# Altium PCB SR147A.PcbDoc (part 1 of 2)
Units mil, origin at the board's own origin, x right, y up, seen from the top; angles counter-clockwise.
Board outline 3000 x 3006 mil, 4 copper layers (Top Layer, Signal Layer 1, Signal Layer 2, Bottom Layer), stack 60.434 mil thick; 65 components, 14 nets, 93 pads, 851 vias.
Unrouted connection lines stored in the file: 2.
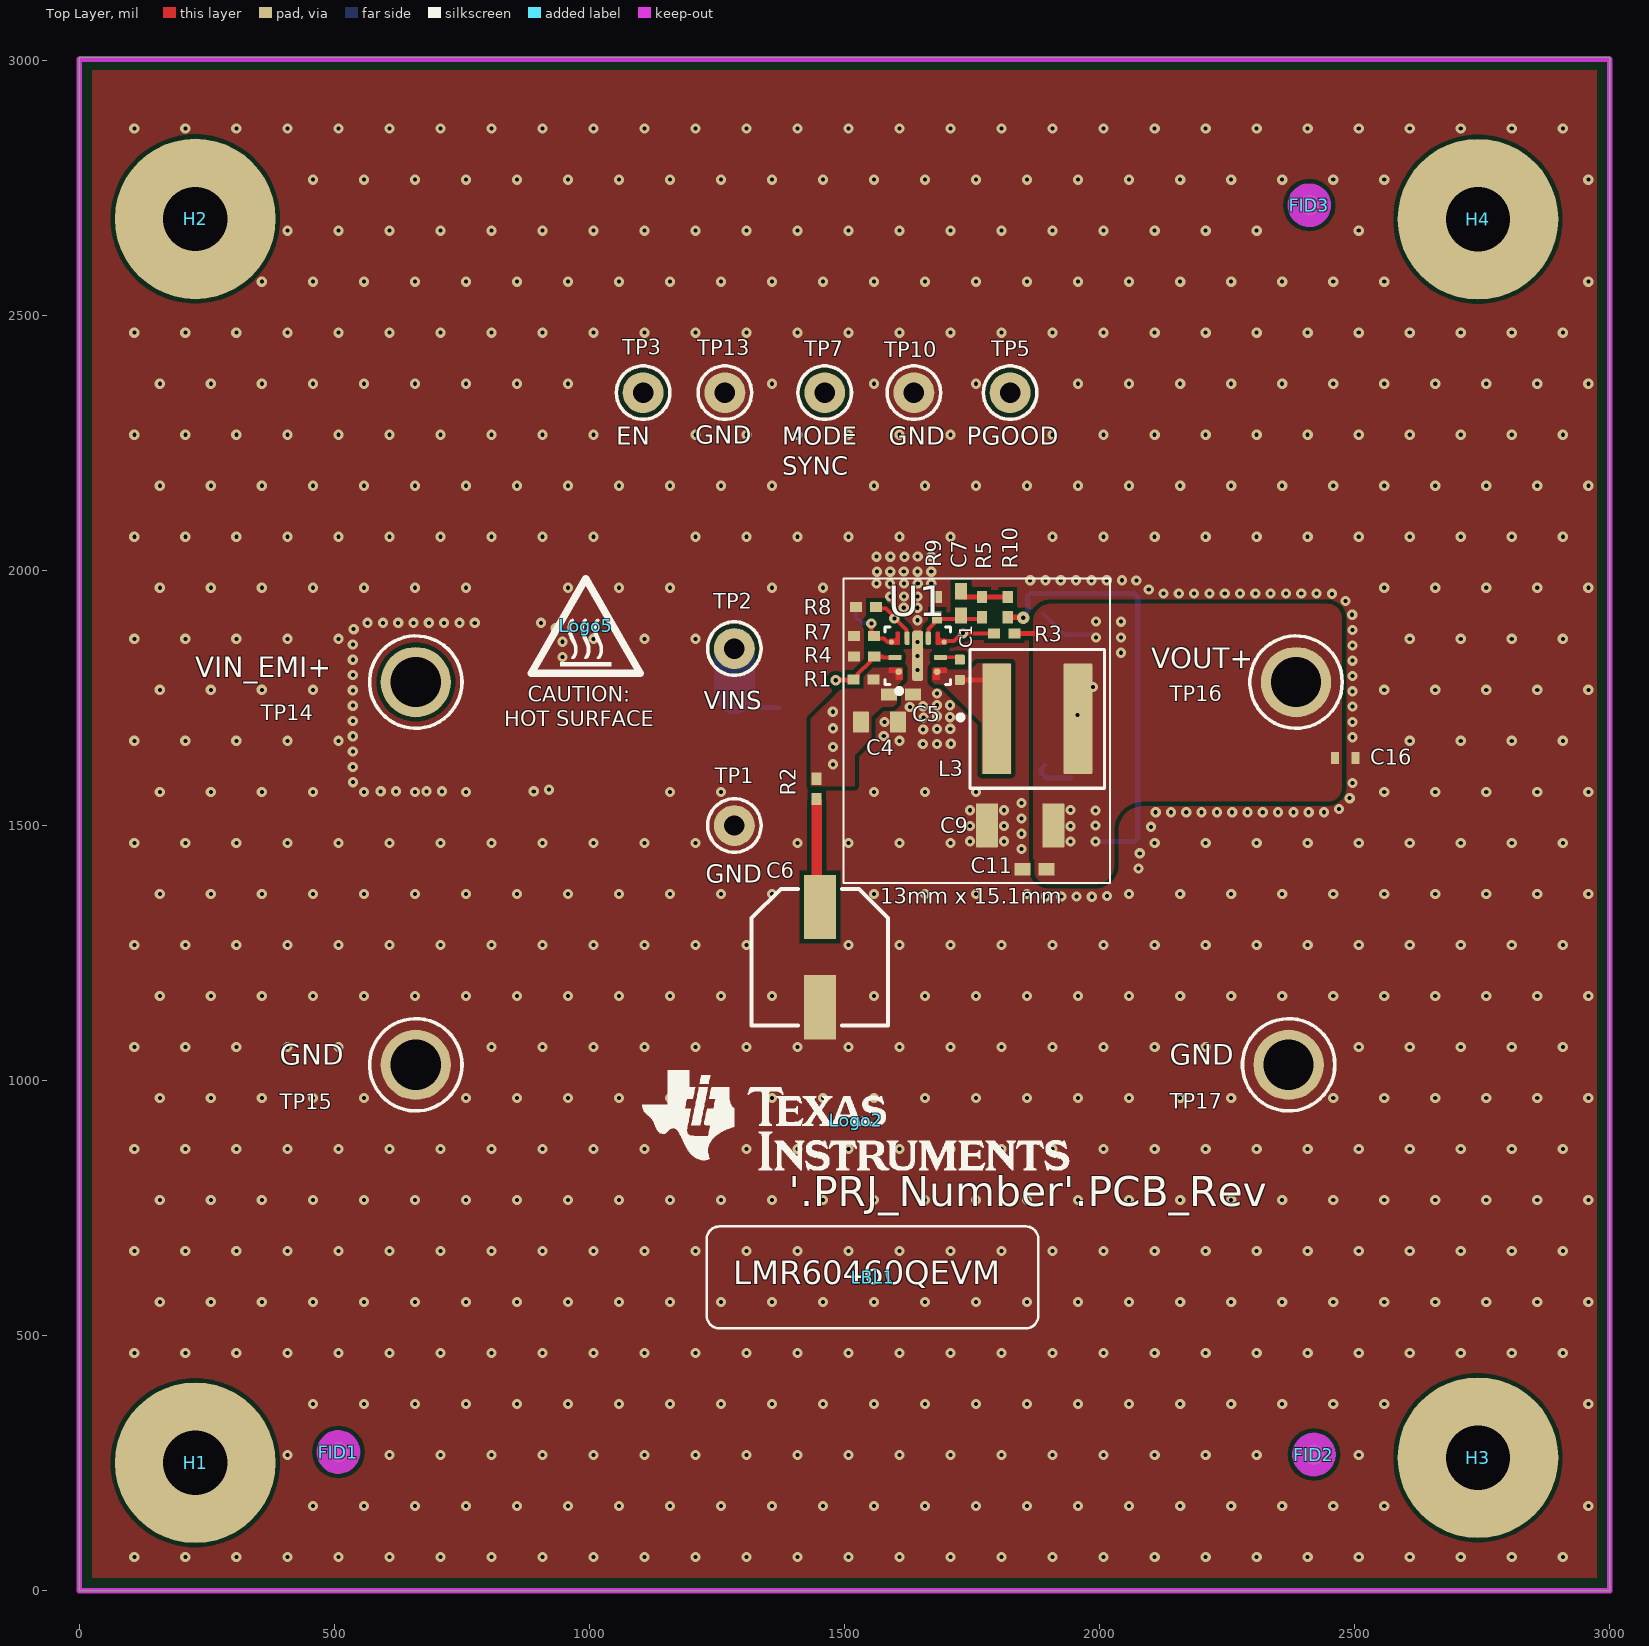
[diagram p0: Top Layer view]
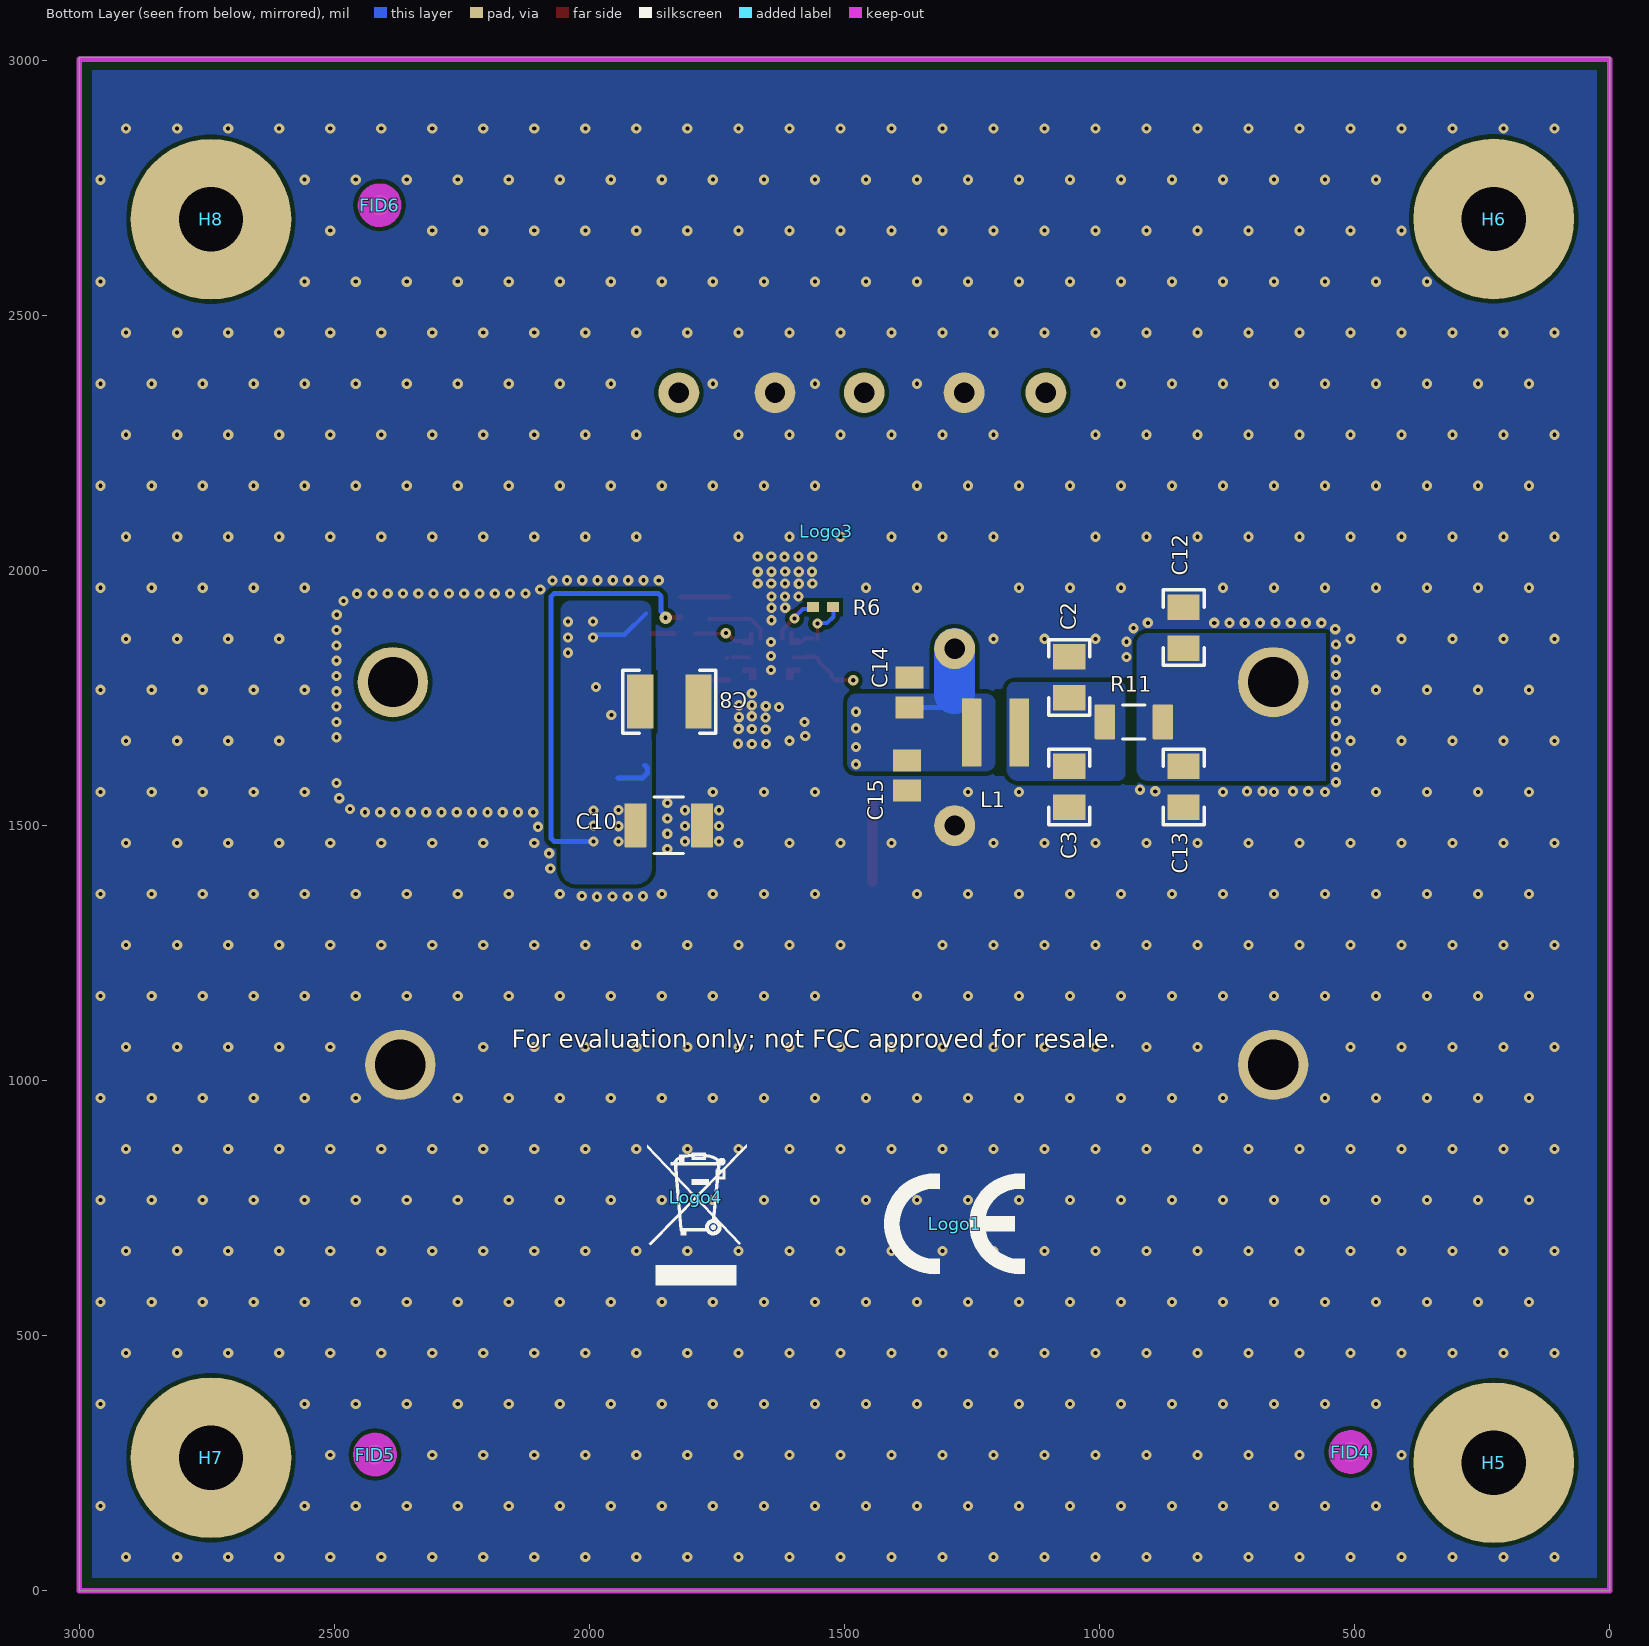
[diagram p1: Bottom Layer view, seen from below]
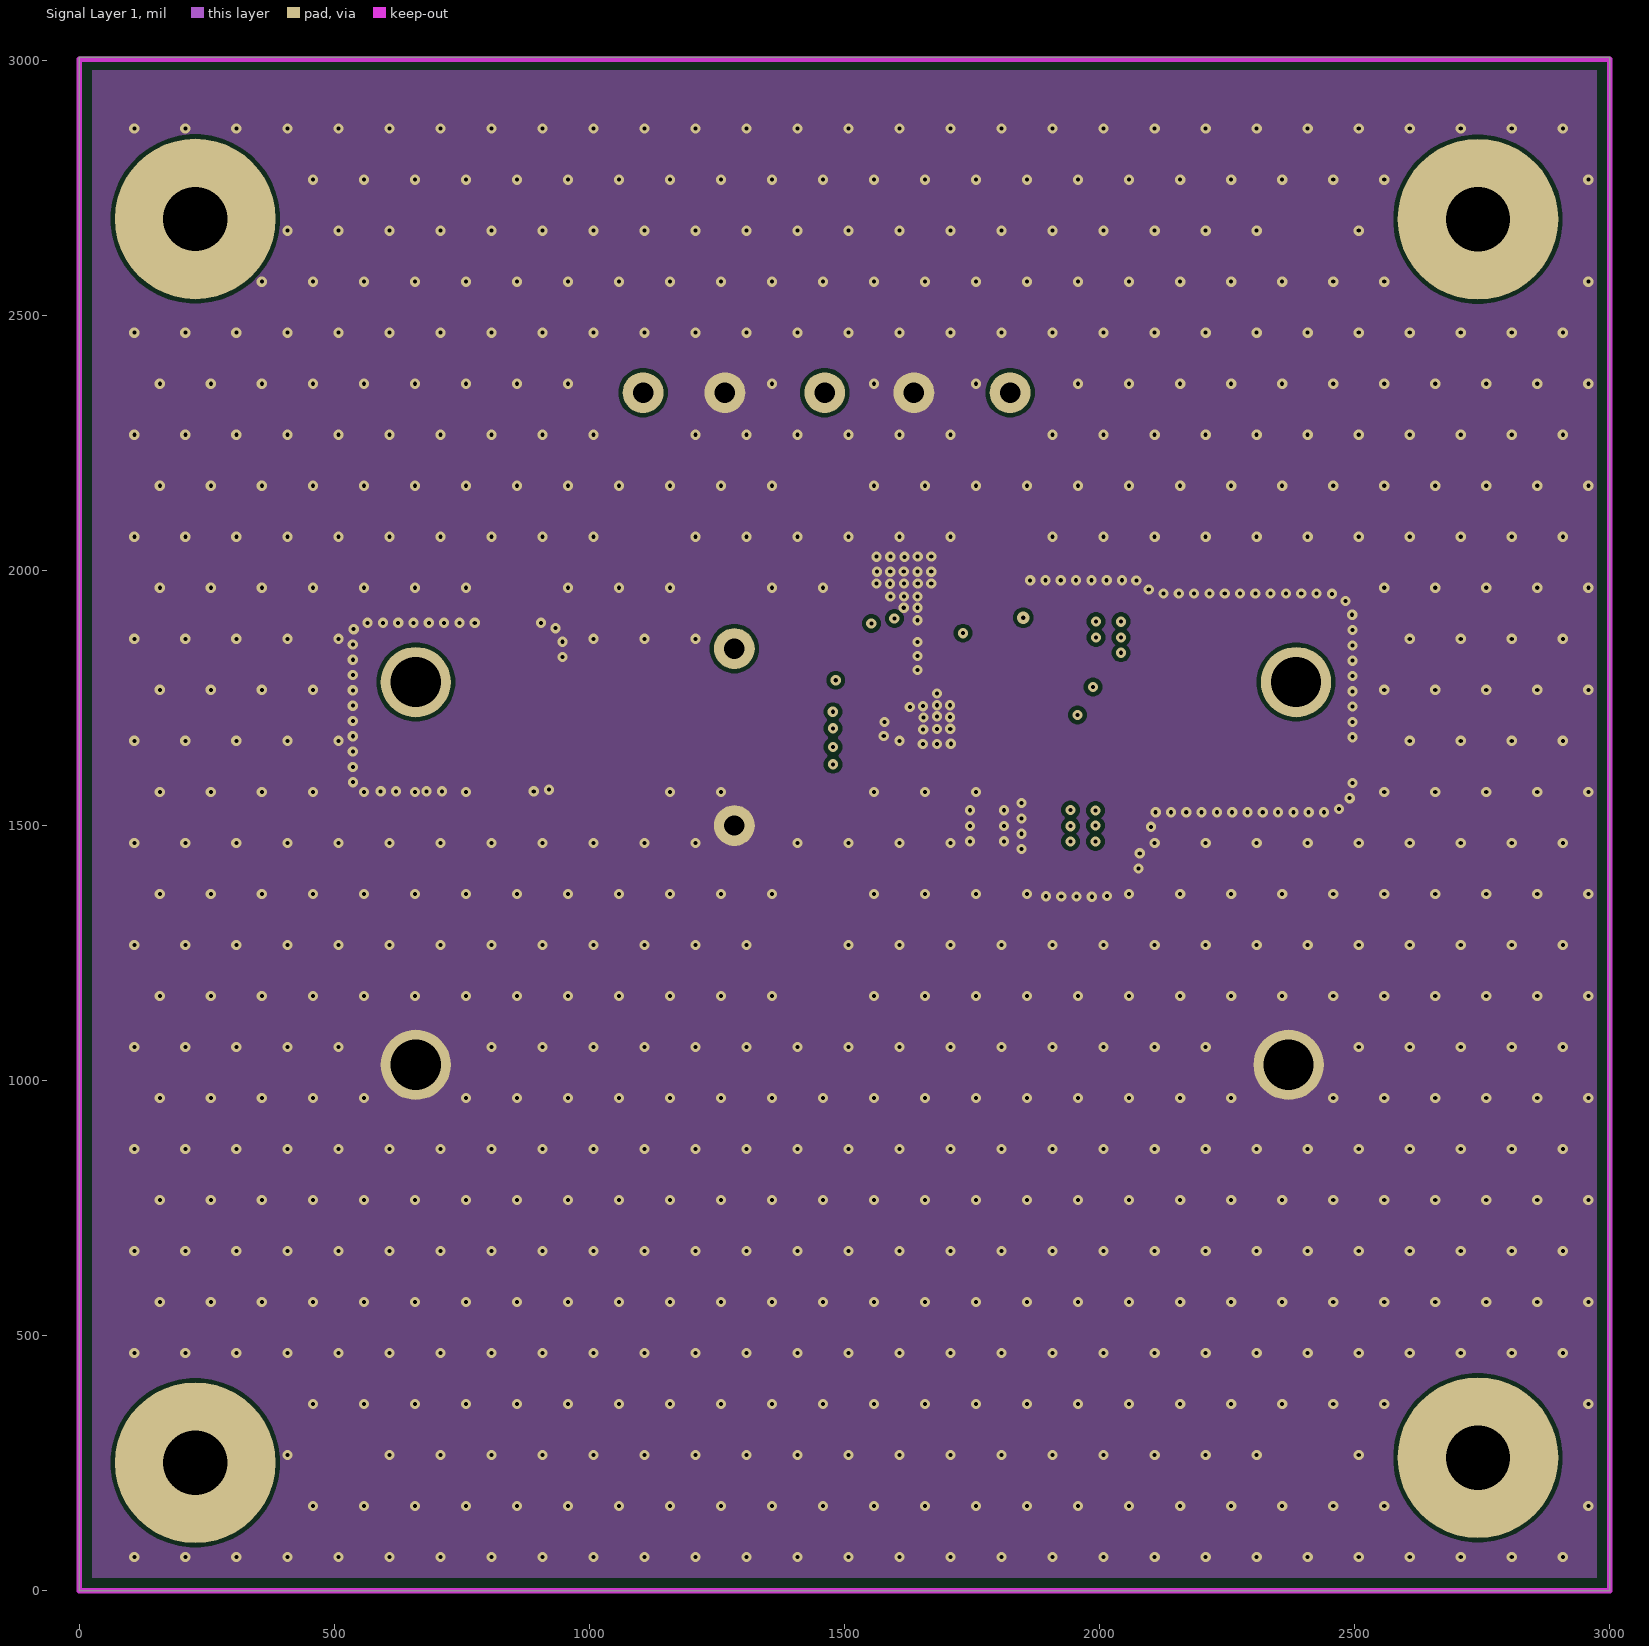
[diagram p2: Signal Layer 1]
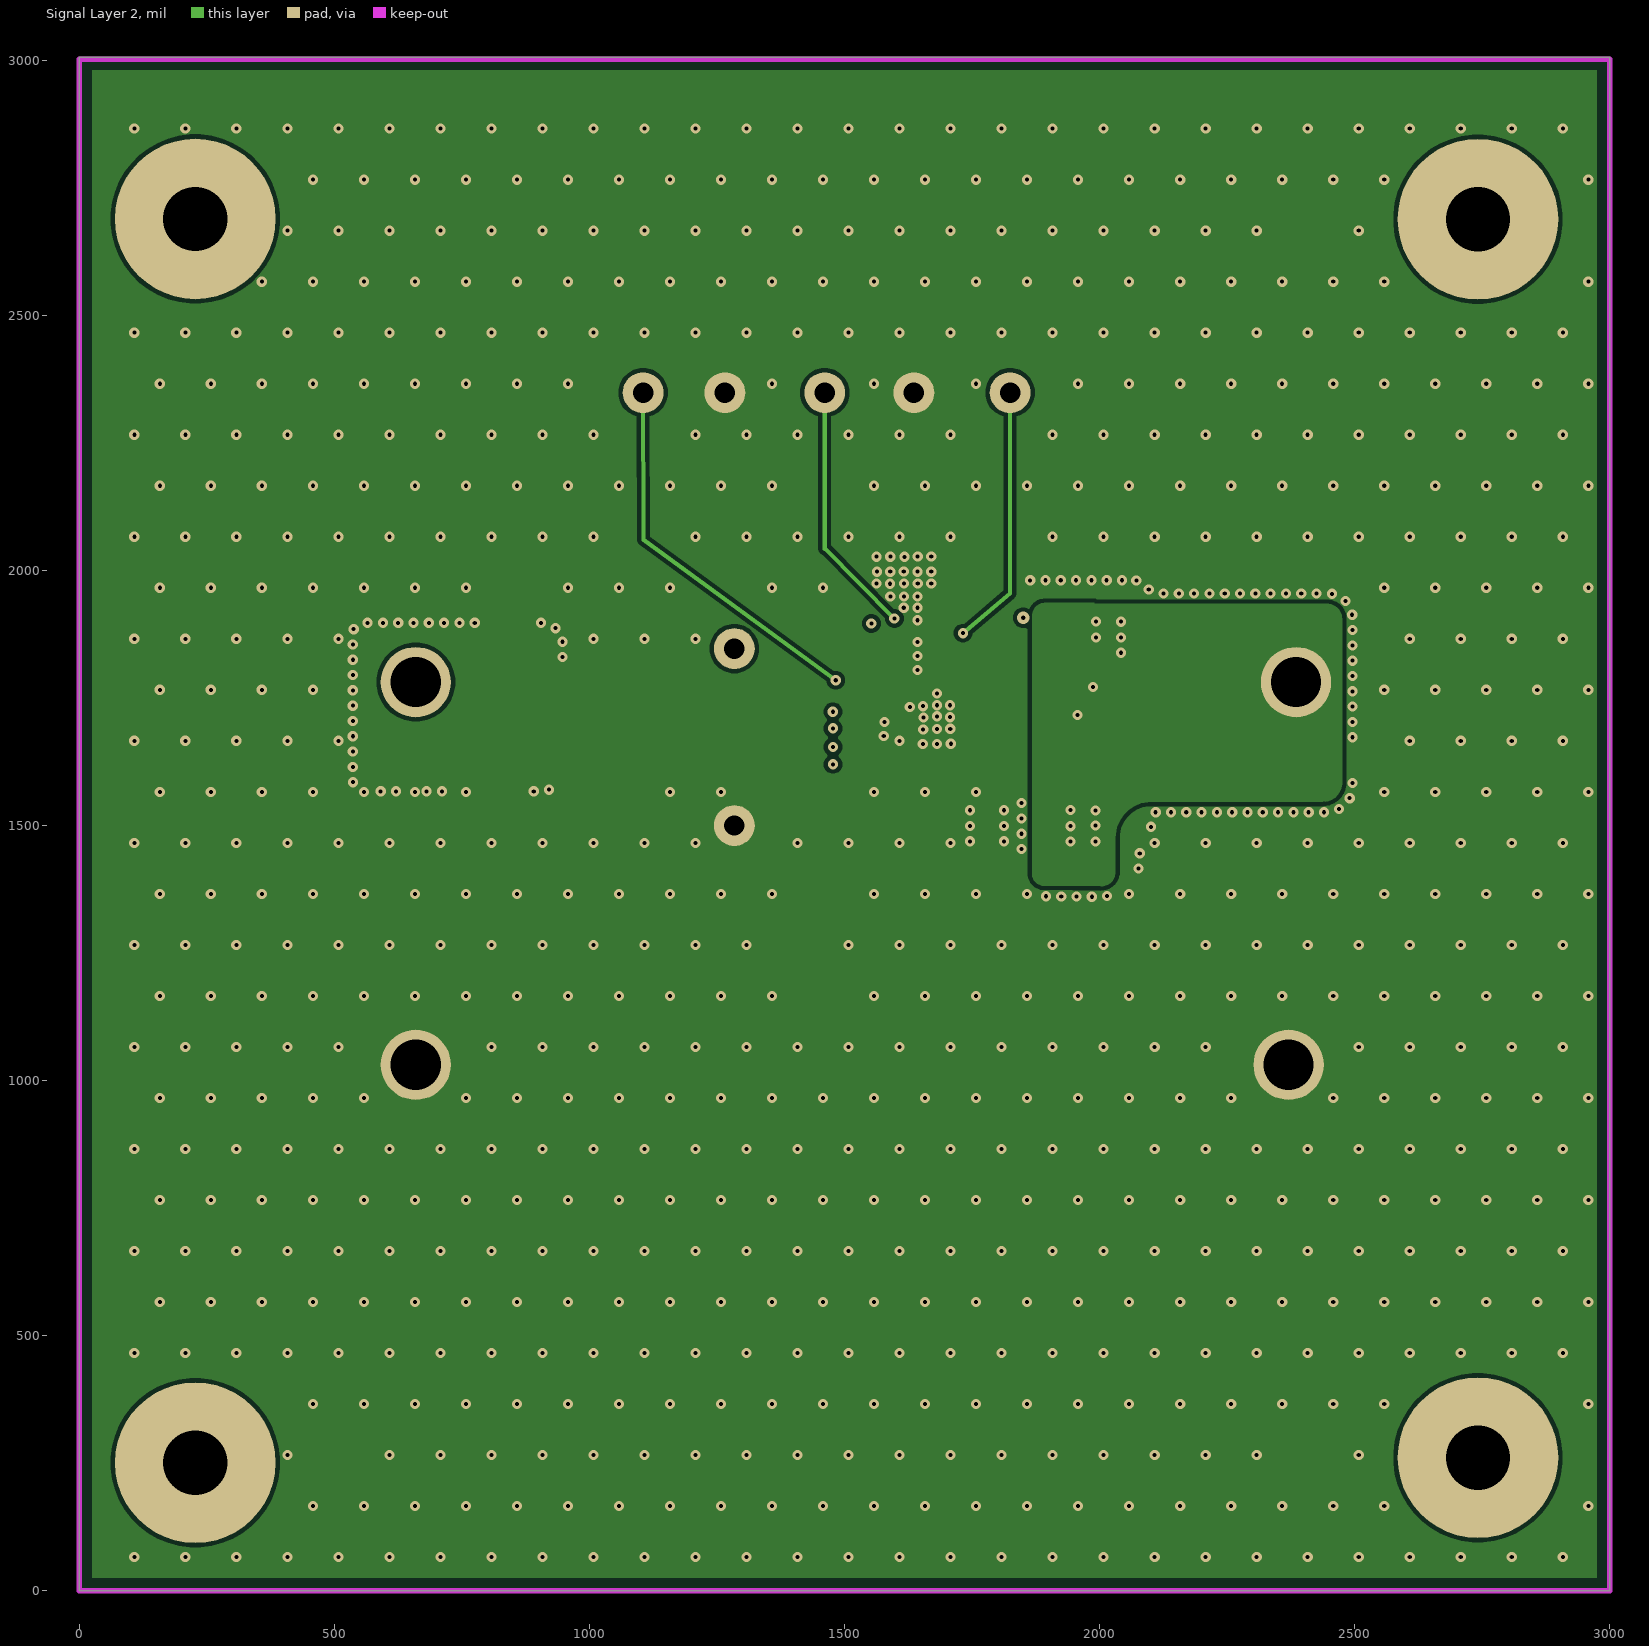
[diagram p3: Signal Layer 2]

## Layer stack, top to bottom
Top Solder: solder mask 0.4, Solder Resist, Dk 3.5
Top Layer: signal copper 2.8
Dielectric 1: core 10, FR-4 High Tg, Dk 4.2
Signal Layer 1: signal copper 1.417
Dielectric2: prepreg 32, FR-4 High Tg, Dk 4.2
Signal Layer 2: signal copper 1.417
Dielectric 3: core 10, FR-4 High Tg, Dk 4.2
Bottom Layer: signal copper 2.8
Bottom Solder: solder mask 0.4, Solder Resist, Dk 3.5

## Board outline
0,0 3000,0 3000,3006 0,3006

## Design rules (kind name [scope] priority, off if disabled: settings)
AcuteAngle [All] p1: minimum=4.50000000000000E+0001 checktracksonly=FALSE
AssemblyTestPointUsage [All] p1: valid=2
BoardOutlineClearance BoardOutlineClearance_MountingHoles [OnCopper and InComponentClass('Mounting Holes')] p1: gap=39.37 ignorepadtopadclearanceinfootprint=FALSE
BoardOutlineClearance BoardOutlineClearance_Poly [OnCopper and IsPoly] p2: gap=25 ignorepadtopadclearanceinfootprint=FALSE
BoardOutlineClearance [OnCopper and Not InComponentClass('Logo') and not InComponentClass('FiducialMark') and not InRegion(1000,500,4000,800) and not InPoly] p3: gap=50 ignorepadtopadclearanceinfootprint=FALSE
Clearance Clearance_Keepouts [((IsTrack Or IsArc) And Not InPoly) And IsFree and IsKeepOut vs ((IsTrack Or IsArc) And Not InPoly) And IsFree and IsKeepOut] p1: gap=0 ignorepadtopadclearanceinfootprint=FALSE
Clearance Clearance_Poly [InPolygon] p2: gap=8 ignorepadtopadclearanceinfootprint=TRUE
Clearance Clearance_FiducialMark [IsKeepOut and InComponentClass('FiducialMark') vs IsPad and InComponentClass('FiducialMark')] p3: gap=0 ignorepadtopadclearanceinfootprint=FALSE
Clearance Clearance_ModeSync [InNet('MODE/SYNC') And OnLayer('Top Layer') vs InNet('GND') And OnLayer('Top Layer')] p4: gap=4.9 ignorepadtopadclearanceinfootprint=FALSE
Clearance Clearance_FB [InNet('FB') And OnLayer('Top Layer') vs InNet('GND') And OnLayer('Top Layer')] p5: gap=4.9 ignorepadtopadclearanceinfootprint=FALSE
Clearance [All] p6: gap=7.9 ignorepadtopadclearanceinfootprint=TRUE except(5.9: SMDPad-Via)
ComponentClearance ComponentClearance_MountingHoles_FiducialMarks [InComponentClass('Mounting Holes') vs InComponentClass('FiducialMark')] p1: gap=50 collisioncheckmode=3 verticalgap=10 showdistances=FALSE
ComponentClearance ComponentClearance_Shunt [InComponentClass('Header') vs InComponentClass('Shunt')] p2: gap=0 collisioncheckmode=3 verticalgap=0 showdistances=FALSE
ComponentClearance ComponentClearance_Logo [InComponentClass('Logo')] p3: gap=50 collisioncheckmode=3 verticalgap=10 showdistances=FALSE
ComponentClearance ComponentClearance_ScrewToNut [(HasFootprint('NY PMS 440 0025 PH')) vs (HasFootprint('Keystone_1902C'))] p4: gap=5 collisioncheckmode=3 verticalgap=10 showdistances=FALSE
ComponentClearance ComponentClearance_MountingHoles [InComponentClass('Mounting Holes')] p5: gap=140 collisioncheckmode=3 verticalgap=100000 showdistances=FALSE
ComponentClearance ComponentClearance_SmallPassives [HasFootprint('0201*') or HasFootprint('0402*') or HasFootprint('0508') or HasFootprint('0603*') or HasFootprint('0612') or HasFootprint('0805*') or HasFootprint('0815*') or HasFootprint('0830*') or HasFootprint('1206*') or HasFootprint('1210*') or HasFootprint('1808*') or HasFootprint('1812*') or HasFootprint('1825*') or HasFootprint('2010*') or HasFootprint('2220*') or HasFootprint('2225*') or HasFootprint('2512*') or HasFootprint('2728*') or HasFootprint('3518*') vs HasFootprint('0201*') or HasFootprint('0402*') or HasFootprint('0508') or HasFootprint('0603*') or HasFootprint('0612') or HasFootprint('0805*') or HasFootprint('0815*') or HasFootprint('0830*') or HasFootprint('1206*') or HasFootprint('1210*') or HasFootprint('1808*') or HasFootprint('1812*') or HasFootprint('1825*') or HasFootprint('2010*') or HasFootprint('2220*') or HasFootprint('2225*') or HasFootprint('2512*') or HasFootprint('2728*') or HasFootprint('3518*')] p6: gap=14.96 collisioncheckmode=3 verticalgap=10 showdistances=FALSE
ComponentClearance ComponentClearance_THtoSMT [IsThruComponent vs IsSMTComponent] p7: gap=40 collisioncheckmode=3 verticalgap=30 showdistances=FALSE
ComponentClearance ComponentClearance_THtoTH [IsThruComponent vs IsThruComponent] p8: gap=30 collisioncheckmode=3 verticalgap=30 showdistances=FALSE
ComponentClearance ComponentClearance_L2 [HasFootprint('FP-XGL4030-222MEC_SMT_IND_4MM0_4MM0-MFG') vs HasFootprint('FP-XGL6060-822MEC_SMT_IND_6MM51_6MM71-MFG')] p9: gap=0 collisioncheckmode=3 verticalgap=0 showdistances=FALSE
ComponentClearance [All] p10: gap=14 collisioncheckmode=3 verticalgap=10 showdistances=FALSE
DiffPairsRouting [All] p1: maxlimit=100 minlimit=10 mostfreqgap=10 toplayer_minwidth=15 toplayer_maxwidth=15 toplayer_prefwidth=15 midlayer1_minwidth=15 midlayer1_maxwidth=15 midlayer1_prefwidth=15 midlayer2_minwidth=15 midlayer2_maxwidth=15 midlayer2_prefwidth=15 bottomlayer_minwidth=15 bottomlayer_maxwidth=15 bottomlayer_prefwidth=15 maxuncoupledlength=1000
FabricationTestPointUsage TestPointUsage [All] p1: valid=2 allowmultiple=FALSE
FabricationTestpoint Testpoint [All] p1: side=3 testpointundercomponent=TRUE minsize=40 maxsize=100 preferedsize=60 minholesize=0 maxholesize=40 preferedholesize=32 testpointgrid=1 allowsidetop=TRUE allowsidebottom=TRUE usegrid=TRUE gridtolerance=0.01
FanoutControl Fanout_LCC [IsLCC] p1: bgadir=Out bgaviamode=Centered fanoutstyle=Auto fanoutdirection=Alternating viagrid=1 // Fanout_LCC (Default Rule)
FanoutControl Fanout_BGA [IsBGA] p2: bgadir=Out bgaviamode=Centered fanoutstyle=Auto fanoutdirection=Alternating viagrid=1 // Fanout_BGA (Default Rule)
FanoutControl Fanout_Default [All] p4: bgadir=Out bgaviamode=Centered fanoutstyle=Auto fanoutdirection=Alternating viagrid=1 // Fanout_Default (Default Rule)
FanoutControl Fanout_Small [(CompPinCount < 5)] p5: bgadir=Out bgaviamode=Centered fanoutstyle=Auto fanoutdirection=OutThenIn viagrid=1 // Fanout_Small (Default Rule)
HoleSize [All] p1: absolutevalues=TRUE maxlimit=251 minlimit=7.87 maxpercent=80.000 minpercent=20.000
MinimumAnnularRing MinimumAnnularRing_ThermalPadVias [IsVia and InAnyComponent] p1: minimumring=5.91
MinimumAnnularRing [All] p2: minimumring=6
MinimumSolderMaskSliver MinimumSolderMaskSliver_Logo [InComponentClass('Logo') vs InComponentClass('Logo')] p1: minsoldermaskwidth=0.7
MinimumSolderMaskSliver [All] p2: minsoldermaskwidth=3.94
PlaneClearance [All] p1: clearance=9.84
PlaneConnect [All] p1: planeconnectstyle=Direct reliefexpansion=10 reliefentries=4 reliefconductorwidth=10 reliefairgap=10
PolygonConnect [All] p1: connectstyle=Direct reliefconductorwidth=10 reliefentries=4 polygonreliefangle="90 Angle" airgapwidth=10
RoutingVias ThermalPadVias [IsVia and InAnyComponent] p1: holewidth=7.87 width=19.68 viastyle="Through Hole" minholewidth=7.87 minwidth=19.68 maxholewidth=12.99 maxwidth=23.62
RoutingVias [All] p2: holewidth=8 width=20 viastyle="Through Hole" minholewidth=7.87 minwidth=19.68 maxholewidth=40 maxwidth=65
SilkToBoardRegionClearance [Not ((IsComment or IsDesignator) And (Hide <> 'False')) and not InRegion(1000,500,4000,800)] p1:
SilkToSilkClearance SilkToSilkClearance_Pb-FreeLogo [(HasFootprint('Pb-Free_Overlay_Medium') OR HasFootprint('Pb-Free_Overlay_Small')) vs (HasFootprint('Pb-Free_Overlay_Medium') OR HasFootprint('Pb-Free_Overlay_Small'))] p1: silktosilkclearance=0
SilkToSilkClearance [All] p2: silktosilkclearance=3.94
SilkToSolderMaskClearance SilkToComponentPadClearance [(IsPad or IsFill or IsRegion) and InAnycomponent] p1: minsilkscreentomaskgap=5 clearancetoexposedcopper=TRUE
SilkToSolderMaskClearance "Silk to Solder Mask Opening" [All] p2: minsilkscreentomaskgap=3.94 clearancetoexposedcopper=FALSE
SolderMaskExpansion [All] p1: expansion=1.97 istentingtop=FALSE
SupplyNets "Schematic Supply Nets" [InNet('GND')] p1: voltage=0.000
UnRoutedNet [All] p1: checkbadconnections=TRUE
Width [All] p1: maxlimit=100 minlimit=6 preferedwidth=10 checkconnectedcopper=TRUE
13 further rules are at their usual default settings.

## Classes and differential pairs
component class SR147_Schematic: C1 C2 C3 C4 C5 C6 C7 C8 C9 C10 C11 C12 C13 C14 C15 C16 L1 L3 R1 R2 R3 R4 R5 R6 R7 R8 R9 R10 R11 TP1 TP2 TP3 TP5 TP7 TP10 TP13 TP14 TP15 TP16 TP17 U1
component class "Mounting Holes": H1 H2 H3 H4
component class Logo: Logo2
component class Label: LBL1
component class SR147_Hardware: !PCB1 FID1 FID2 FID3 FID4 FID5 FID6 H1 H2 H3 H4 H5 H6 H7 H8 LBL1 Logo1 Logo2 Logo3 Logo4 Logo5 ZZ1 ZZ2 ZZ3 ZZ4
component class FiducialMark: FID1 FID2 FID3 FID4 FID5 FID6
component class AssemblyNote: ZZ1 ZZ2 ZZ3 ZZ4

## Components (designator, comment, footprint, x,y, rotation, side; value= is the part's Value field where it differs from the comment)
C1 "CS0402KRX7R8BB104" FP-CS0402KRX7R8BB104_0402-MFG 1726.01,1805.33 r270 top value=100nF
C2 "CGA4J3X7R1H225K125AB" 0805_HV 1059.28,1790.53 r90 bottom value=2.2uF
C3 "CGA4J3X7R1H225K125AB" 0805_HV 1059.28,1575.89 r270 bottom value=2.2uF
C4 "C2012X7R1H475K125AC" FP-C2012X7R1H475K125AC_0805-MFG 1568.41,1702.94 r180 top
C5 "GCM155R71H104KE02D" 0402 1610.59,1756.75 r0 top value=0.1uF
C6 "EEEFT1H470AP" Panasonic_D 1451.8,1242 r270 top value=47uF
C7 "CGA2B2C0G1H220J050BA" 0402 1728.46,1935.62 r270 top value=22pF
C8 "GRM32ER61C476KE15L" 1210_270 1843.13,1742.97 r180 bottom value=47uF
C9 "CGA6P1X7R1C226M250AC" FP-CGA6P1X7R1C226M250AC_1210-MFG 1844.38,1500.35 r0 top value=22µF
C10 "CGA6P1X7R1C226M250AC" FP-CGA6P1X7R1C226M250AC_1210-MFG 1844.38,1500.35 r0 bottom value=22µF
C11 "GCM155R71H104KE02D" 0402 1872.74,1414.3 r180 top value=0.1uF
C12 "CGA4J3X7R1H225K125AB" 0805_HV 835.16,1887.93 r90 bottom value=2.2uF
C13 "CGA4J3X7R1H225K125AB" 0805_HV 835.16,1575.89 r270 bottom value=2.2uF
C14 "CGA4J3X7R1H225K125AB" 0805L 1372.16,1761 r90 bottom value=2.2uF
C15 "CGA4J3X7R1H225K125AB" 0805L 1377.78,1598.08 r270 bottom value=2.2uF
C16 "GCM155R71H104KE02D" 0402S 2481.54,1632.29 r0 top value=0.1uF
FID1 "Fiducial" Fiducial10-20 508.09,272 r0 top
FID2 "Fiducial" Fiducial10-20 2420.16,267 r0 top
FID3 "Fiducial" Fiducial10-20 2411.16,2716 r0 top
FID4 "Fiducial" Fiducial10-20 508.09,272 r180 bottom
FID5 "Fiducial" Fiducial10-20 2420.16,267 r180 bottom
FID6 "Fiducial" Fiducial10-20 2411.16,2716 r180 bottom
H1 "NY PMS 440 0025 PH" "NY PMS 440 0025 PH" 227.5,251 r0 top
H2 "NY PMS 440 0025 PH" "NY PMS 440 0025 PH" 227.5,2689.03 r0 top
H3 "NY PMS 440 0025 PH" "NY PMS 440 0025 PH" 2741.72,261 r0 top
H4 "NY PMS 440 0025 PH" "NY PMS 440 0025 PH" 2741.72,2688.54 r0 top
H5 "1902C" Keystone_1902C 227.5,251 r180 bottom
H6 "1902C" Keystone_1902C 227.5,2688.54 r180 bottom
H7 "1902C" Keystone_1902C 2741.72,261 r180 bottom
H8 "1902C" Keystone_1902C 2741.72,2688.54 r180 bottom
L1 "XEL4020-222MEB" XEL4020 1204.16,1682.27 r0 bottom value=2.2uH
L3 "XGL6060-332MEC" FP-XGL6060-332MEC_SMT_6MM51_6MM71-MFG 1878.05,1709.11 r0 top value=3.3uH
LBL1 "THT-14-423-10" Label_650x200 1555.04,614.3 r0 top
Logo1 "CE Mark" CE_Mark_5mm 1284.16,719.35 r180 bottom
Logo2 "Texas Instruments" TI_Stacked_Overlay_Small 1521.81,922 r0 top
Logo3 "FCC disclaimer" FCC_disclaimer 1536.16,2077 r180 bottom
Logo4 "WEEE logo" WEEE_Minimum 1791.16,771 r180 bottom
Logo5 "CAUTION HOT SURFACE" IEC_HotSurface_Small 992.89,1891.57 r0 top
R1 "CRCW040230K1FKED" 0402L 1537.62,1786.29 r0 top value=30.1k
R2 "RC0402JR-070RL" 0402L 1445.44,1572.05 r90 top value=0
R3 "CRCW0402100KJNED" 0402L 1813.16,1876.41 r180 top value=100k
R4 "AC0402FR-0710KL" 0402L 1538.71,1830.89 r0 top value=10.0k
R5 "RC0402JR-070RL" 0402L 1769.16,1927.92 r90 top value=0
R6 "RC0402JR-070RL" 0402L 1542.43,1927.92 r0 bottom value=0
R7 "CRCW040286K6FKED" 0402L 1538.41,1871.37 r0 top value=86.6k
R8 "RC0402JR-070RL" 0402L 1542.43,1928.12 r0 top value=0
R9 "MCS0402MD1002BE100" 0402L 1681.59,1927.92 r270 top value=10.0k
R10 "RC0402JR-070RL" 0402L 1820.07,1927.92 r270 top value=0
R11 "5108" FP-5108_1206-MFG 932.85,1702.97 r0 bottom value=0
TP1 "5001" Keystone5001 1284.16,1500 r90 top
TP2 "5000" Keystone5000 1284.16,1846.84 r90 top
TP3 "5000" Keystone5000 1105.22,2348.47 r180 top
TP5 "5002" Keystone5002 1824.61,2348.47 r0 top
TP7 "5004" Keystone5004 1461.3,2348.47 r0 top
TP10 "5001" Keystone5001 1636.16,2348.47 r0 top
TP13 "5001" Keystone5001 1265.61,2348.47 r0 top
TP14 "1502-2" Keystone1502-2 659.7,1781.12 r0 top
TP15 "1502-2" Keystone1502-2 659.7,1031.05 r0 top
TP16 "1502-2" Keystone1502-2 2385.16,1781.12 r0 top
TP17 "1502-2" Keystone1502-2 2370.61,1031.05 r0 top
U1 "LMR604605SVBC" VBC0009A-MFG 1643.56,1832.61 r90 top
ZZ1 "This Assembly Note is for PCB labels only" AssemblyNoteLabel 86,4240 r0 top
ZZ2 "These assemblies are ESD sensitive, ESD precautions shall be observed." AssemblyNote 86,4127 r0 top
ZZ3 "These assemblies must be clean and free from flux and all contaminants. Use of no clean flux is not acceptable." AssemblyNote 87,4003 r0 top
ZZ4 "These assemblies must comply with workmanship standards IPC-A-610 Class 2, unless otherwise specified." AssemblyNote 82,3873 r0 top

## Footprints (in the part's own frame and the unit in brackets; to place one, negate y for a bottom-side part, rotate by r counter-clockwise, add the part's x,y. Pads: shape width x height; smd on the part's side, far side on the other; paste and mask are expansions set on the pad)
0402 [mm] "0402 from SM-752 data"
  rect 0.8x0.6 smd: 1(-0.6,0) 2(0.6,0)
  body extent -0.55,-0.3 0.55,0.3, height 0.6
0402L [mm] "0402 from SM-752 data"
  rect 0.6x0.5 smd: 1(-0.5,0) 2(0.5,0)
  body extent -0.55,-0.3 0.55,0.3, height 0.6
0402S [mil] "Based on C0402S footprint from PADS legacy"
  rect 15x24 smd: 1(-20,0) 2(20,0)
  body extent -22,-12 22,12, height 24
0805_HV [mil] "0805 with 30mil clearance between pads"
  rect 50x63 smd: 1(-40,0) 2(40,0)
  silkscreen extent -74,-40 74,40, body extent -43,-29 43,29, height 57
0805L [mm] "0805 from SM-752 data"
  rect 1.1x1.4 smd: 1(-0.75,0) 2(0.75,0)
  body extent -1.1,-0.72 1.1,0.72, height 1.45
1210_270 [mm] "1210"
  rect 1.3x2.7 smd: 1(-1.45,0) 2(1.45,0)
  silkscreen extent -2.32,-1.57 2.32,1.57, body extent -1.7,-1.35 1.7,1.35, height 2.7
AssemblyNote [mil] "Assembly Note"
AssemblyNoteLabel [mil] "Assembly Note for PCB Labels"
CE_Mark_5mm [mil] "Minimum text height for CE Mark"
  silkscreen extent -138,-98 138,98
FCC_disclaimer [mil]
Fiducial10-20 [mm]
  round 1 smd mask+0.5: 1(0,0)
  Top Layer keep-out circle w1.178: c0,0 r0.5
FP-5108_1206-MFG [mm]
  rrect10% 1.01x1.73 smd paste+0 mask+0: 1(-1.445,0) 2(1.445,0)
  silkscreen extent -0.57,-0.85 0.57,0.85, body extent -1.53,-0.85 1.53,0.85, height 0.71
FP-C2012X7R1H475K125AC_0805-MFG [mm]
  rrect13% 0.8x1.05 smd paste+0 mask+0: 1(-0.925,0) 2(0.925,0)
  body extent -1.43,-0.85 1.43,0.85, height 0.25
FP-CGA6P1X7R1C226M250AC_1210-MFG [mm]
  rrect9% 1.1x2.2 smd paste+0 mask+0: 1(-1.65,0) 2(1.65,0)
  body extent -2.3,-1.5 2.3,1.5, height 0.25
FP-CS0402KRX7R8BB104_0402-MFG [mm]
  rrect20% 0.5x0.5 smd paste+0 mask+0: 1(-0.5,0) 2(0.5,0)
  body extent -0.87,-0.48 0.87,0.48, height 0.25
FP-XGL6060-332MEC_SMT_6MM51_6MM71-MFG [mm]
  rrect7% 1.43x5.5 smd paste+0 mask+0: 1(-2.02,0) 2(2.02,0)
  silkscreen extent -3.95,-3.45 3.35,3.45, body extent -3.45,-3.55 3.45,3.55, height 0.25
IEC_HotSurface_Small [mil]
  silkscreen extent -107,-93 107,92
Keystone1502-2 [mm] "Double Turret"
  round 3.5 hole 2.5: 1(0,0)
  silkscreen extent -2.3,-2.3 2.3,2.3, body extent -1.6,-1.6 1.59,1.6, height 5.62
Keystone5000 [mil] "For Keystone 500x miniature loop terminals"
  round 80 hole 40: 1(0,0)
  silkscreen extent -52,-52 52,52, body extent -49,-49 49,49, height 182
Keystone5001 [mil] "For Keystone 500x miniature loop terminals"
  round 80 hole 40: 1(0,0)
  silkscreen extent -52,-52 52,52, body extent -49,-49 49,49, height 182
Keystone5002 [mil] "For Keystone 500x miniature loop terminals"
  round 80 hole 40: 1(0,0)
  silkscreen extent -52,-52 52,52, body extent -49,-49 49,49, height 182
Keystone5004 [mil] "For Keystone 500x miniature loop terminals"
  round 80 hole 40: 1(0,0)
  silkscreen extent -52,-52 52,52, body extent -49,-49 49,49, height 182
Keystone_1902C [mil] "Hex Standoff, 4-40 threaded, nylon"
  round 1 on Mech4: 0(0,0)
  body extent -145,-126 146,126, height 501
Label_650x200 [mil] "Thermal Transfer Label"
  round 1 on Mech13: 0(0,0)
  silkscreen extent -325,-100 325,100, body extent -325,-100 325,100, height 1
"NY PMS 440 0025 PH" [mm] "4-40 nylon screw and mounting hole"
  round 8 hole 3.2: 1(0,0)
  body extent -3.3,-3.3 3.3,3.3, height 2.69
Panasonic_D [mm] "SMD, 2-Leads, Dia 6.3mm"
  rect 3.2x1.6 smd: 1(-2.5,0) 2(2.5,0)
  silkscreen extent -3.4,-3.4 3.4,3.4, body extent -3.4,-3.4 3.4,3.4, height 6.11
TI_Stacked_Overlay_Small [mil]
  silkscreen extent -418,-98 418,98
VBC0009A-MFG [mm] "Recommended Land Pattern"
  round 0.337 smd paste-1000 mask+0: 1(-0.787,0.943) 3(-0.787,-0.962)
  rrect36% 2.5x0.55 smd paste-1000 mask-1000: 2(0,0)
  rrect40% 0.25x0.65 smd paste+0 mask+0: 4(-0.075,-1.125) 9(-0.075,1.125)
  round 0.247 smd paste+0 mask+0: 5(0.687,-1.312) 8(0.687,1.312)
  rrect40% 0.65x0.25 smd paste+0 mask+0: 6(0.875,-0.525) 7(0.875,0.525)
  Top Layer region: -1.15,0.755 -1.169,0.759 -1.185,0.77 -1.196,0.786 -1.2,0.805 -1.2,0.805 -1.2,1.05 -1.193,1.075 -1.175,1.093 -1.15,1.1 -1.15,1.1 -0.95,1.1 -0.912,1.108 -0.879,1.129 -0.858,1.162 -0.85,1.2 -0.85,1.2 -0.85,1.4 -0.843,1.425 -0.825,1.443 -0.8,1.45 -0.8,1.45 -0.65,1.45 -0.631,1.446 -0.615,1.435 -0.604,1.419 -0.6,1.4 -0.6,1.4 -0.6,0.805 -0.604,0.786 -0.615,0.77 -0.631,0.759 -0.65,0.755 -0.65,0.755
  Top Layer region: -1.15,-0.755 -1.169,-0.759 -1.185,-0.77 -1.196,-0.786 -1.2,-0.805 -1.2,-0.805 -1.2,-1.05 -1.196,-1.069 -1.185,-1.085 -1.169,-1.096 -1.15,-1.1 -1.15,-1.1 -0.95,-1.1 -0.912,-1.108 -0.879,-1.129 -0.858,-1.162 -0.85,-1.2 -0.85,-1.2 -0.85,-1.4 -0.846,-1.419 -0.835,-1.435 -0.819,-1.446 -0.8,-1.45 -0.8,-1.45 -0.65,-1.45 -0.631,-1.446 -0.615,-1.435 -0.604,-1.419 -0.6,-1.4 -0.6,-1.4 -0.6,-0.805 -0.604,-0.786 -0.615,-0.77 -0.631,-0.759 -0.65,-0.755 -0.65,-0.755
  Top Layer region: 1.15,-0.9 1.169,-0.904 1.185,-0.915 1.196,-0.931 1.2,-0.95 1.2,-0.95 1.2,-1.05 1.193,-1.075 1.175,-1.093 1.15,-1.1 1.15,-1.1 0.95,-1.1 0.912,-1.108 0.879,-1.129 0.858,-1.162 0.85,-1.2 0.85,-1.2 0.85,-1.4 0.843,-1.425 0.825,-1.443 0.8,-1.45 0.8,-1.45 0.6,-1.45 0.581,-1.446 0.565,-1.435 0.554,-1.419 0.55,-1.4 0.55,-1.4 0.55,-0.95 0.554,-0.931 0.565,-0.915 0.581,-0.904 0.6,-0.9 0.6,-0.9
  Top Layer region: 1.15,0.9 1.169,0.904 1.185,0.915 1.196,0.931 1.2,0.95 1.2,0.95 1.2,1.05 1.196,1.069 1.185,1.085 1.169,1.096 1.15,1.1 1.15,1.1 0.95,1.1 0.912,1.108 0.879,1.129 0.858,1.162 0.85,1.2 0.85,1.2 0.85,1.4 0.846,1.419 0.835,1.435 0.819,1.446 0.8,1.45 0.8,1.45 0.6,1.45 0.581,1.446 0.565,1.435 0.554,1.419 0.55,1.4 0.55,1.4 0.55,0.95 0.554,0.931 0.565,0.915 0.581,0.904 0.6,0.9 0.6,0.9
  silkscreen extent -1.87,-1.63 1.43,1.63, body extent -1,-1.25 1,1.25, height 0.7
WEEE_Minimum [mil] "WEEElie bin"
  silkscreen extent -95,-172 99,104
XEL4020 [mm] "SMD, 2-Leads, Body 4x4mm, Pitch 2.37mm"
  rrect10% 0.98x3.4 smd: 1(-1.185,0) 2(1.185,0)
  body extent -2.15,-2.15 2.15,2.15, height 2.1

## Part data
C1: library part CMP-0050130-1, "0.1 µF ±10% 25V Ceramic Capacitor X7R 0402 (1005 Metric)", Digikey Part Number=13-CS0402KRX7R8BB104CT-ND, Manufacturer=Yageo, Mouser Part Number=603-CS0402KRX78BB104, Operating Temperature Range="-55°C to +125°C", TempCo=15%, Temperature Characteristic=X7R, Tolerance_%=10%, ValueDisplayed=100nF
C2 C3 C12 C13 C14 C15: library part CMP-0007977-2, "CAP, CERM, 2.2 uF, 50 V, +/- 10%, X7R, AEC-Q200 Grade 1, 0805", Cap_Case=0805, Manufacturer=TDK, Supplier Part Number 1=445-174216-1-ND, TempCo=X7R, Tolerance_%=10%, Value1="0.003288 ohm", Value2=50V, ValueDisplayed=2.2uF
C4: library part CMP-0088943-1, "4.7µF ±10% 50V Ceramic Capacitor X7R 0805 (2012 Metric)", Digikey Part Number=445-C2012X7R1H475K125ACCT-ND, Manufacturer=TDK, Mouser Part Number=810-C2012X7R475K125C, Operating Temperature Range="-55°C to +125°C", TempCo=15%, Temperature Characteristic=X7R, Tolerance_%=10%, ValueDisplayed=4.7uF
C5 C11 C16: library part CMP-0006356-2, "CAP, CERM, 0.1 uF, 50 V, +/- 10%, X7R, AEC-Q200 Grade 1, 0402", Cap_Case=0402, Manufacturer=MuRata, Supplier Part Number 1=490-10672-1-ND, TempCo=X7R, Tolerance_%=10%, Value1=Unknown, Value2=50V, ValueDisplayed=0.1uF
C6: library part CMP-0011204-2, "CAP, AL, 47 uF, 50 V, +/- 20%, 0.68 ohm, AEC-Q200 Grade 2, SMD", Cap_Case=6.3x5.8mm, Manufacturer=Panasonic, Supplier Part Number 1=PCE5023CT-ND, Tolerance_%=20%, Value1="0.68 ohm", Value2=50V, ValueDisplayed=47uF
C7: library part CMP-0860831-1, "CAP, CERM, 22 pF, 50 V,+/- 5%, C0G/NP0, AEC-Q200 Grade 1, 0402", Cap_Case=0402, Manufacturer=TDK, TempCo=C0G/NP0, Tolerance_%=5%, Value2=50V, ValueDisplayed=22pF
C8: library part CMP-0009211-2, "CAP, CERM, 47 uF, 16 V, +/- 10%, X5R, 1210", Cap_Case=1210, Manufacturer=MuRata, Supplier Part Number 1=GRM32ER61C476KE15L-ND, TempCo=X5R, Tolerance_%=10%, Value1=Unknown, Value2=16V, ValueDisplayed=47uF
C9 C10: library part CMP-0043794-1, "Cap Ceramic 22uF 16V X7R 20% Pad SMD 1210 +125°C Automotive T/R", Manufacturer=TDK, Operating Temperature Range="-55°C to +125°C", TempCo=15%, Temperature Characteristic=X7R, Tolerance_%=0.2%, ValueDisplayed=22uF
FID1 FID2 FID3 FID4 FID5 FID6: library part CMP-0077181-1, "Fiducial mark.  There is nothing to buy or mount.", Manufacturer=N/A
H1 H2 H3 H4: library part CMP-0003617-1, "Machine Screw, Round, #4-40 x 1/4, Nylon, Philips panhead", Manufacturer="B&F Fastener Supply", Supplier Part Number 1=H542-ND
H5 H6 H7 H8: library part CMP-0003610-1, "Standoff, Hex, 0.5\"L #4-40 Nylon", Manufacturer=Keystone, Supplier Part Number 1=36-1902C-ND
L1: library part CMP-0061079-2, "Inductor, Shielded, Composite, 2.2 uH, 5.5 A, 0.0362 ohm, AEC-Q200 Grade 1, SMD", Manufacturer=Coilcraft, Value1="0.0362 ohm", Value2=5.5A, ValueDisplayed=2.2uH
L3: library part CMP-0093175-1, "Shielded Power Inductors 3.3uH 20% tol, 6.5mOhm 16.6A", Manufacturer=Coilcraft, Operating Temperature Range=to, Self Resonant Frequency=24MHz, Test Frequency=1MHz, Tolerance_%=20%
LBL1: library part CMP-0003625-1, "Thermal Transfer Printable Labels, 0.650\" W x 0.200\" H - 10,000 per roll", Manufacturer=Brady, Supplier Part Number 1=97C5133
Logo1: library part CMP-0074844-2, Manufacturer="Texas Instruments"
Logo2: library part CMP-0074838-1, "Texas Instrument Corporate Signature"
Logo3: library part CMP-0074847-1, "FCC_disclaimer"
Logo4: library part CMP-0074769-4, Manufacturer="Texas Instruments"
Logo5: library part CMP-0074837-2, "IEC 61010-1 Hot Surface Warning", Manufacturer="Texas Instruments"
R1: library part CMP-0026284-2, "RES, 30.1 k, 1%, 0.063 W, AEC-Q200 Grade 0, 0402", Manufacturer=Vishay-Dale, Power_W=63mW, Supplier Part Number 1=541-30.1KLCT-ND, TempCo="100 ppm/C", Tolerance_%=1%, Value2=0.063W, Value_Code=30k1, ValueDisplayed=30.1k
R2 R5 R6 R8 R10: library part CMP-0027004-2, "RES, 0, 5%, 0.063 W, 0402", Manufacturer="Yageo America", Power_W=63mW, Supplier Part Number 1=311-0.0JRCT-ND, TempCo="200 ppm/C", Tolerance_%=5%, Value2=0.063W, Value_Code=0000, ValueDisplayed=0
R3: library part CMP-0026823-3, "RES, 100 k, 5%, 0.063 W, AEC-Q200 Grade 0, 0402", Manufacturer=Vishay-Dale, Power_W=63mW, Supplier Part Number 1=541-100KJCT-ND, TempCo="200 ppm/C", Tolerance_%=5%, Value2=0.063W, Value_Code=100k
R4: library part CMP-0077731-1, "RES, 10.0 k, 1%, 0.063 W, AEC-Q200 Grade 0, 0402", Manufacturer="Yageo America", Power_W=63mW, Supplier Part Number 1=YAG3436CT-ND, TempCo="100 ppm/C", Tolerance_%=1%, Value2=0.063W, Value_Code=10k0, ValueDisplayed=10.0k
R7: library part CMP-0026582-2, "RES, 86.6 k, 1%, 0.063 W, AEC-Q200 Grade 0, 0402", Manufacturer=Vishay-Dale, Power_W=63mW, Supplier Part Number 1=541-86.6KLCT-ND, TempCo="100 ppm/C", Tolerance_%=1%, Value2=0.063W, Value_Code=86k6, ValueDisplayed=86.6k
R9: library part CMP-0077124-1, "RES, 10.0 k, 0.1%, 0.1 W, AEC-Q200 Grade 0, 0402", Manufacturer=Vishay/Beyschlag, Power_W=100mW, Supplier Part Number 1=MCS0402-10.0K-MBCT-ND, TempCo="25 ppm/C", Tolerance_%=0.1%, Value2=0.1W, Value_Code=10k0, ValueDisplayed=10.0k
R11: library part CMP-0122408-1, "0 Ohms Jumper 0.5W, 1/2W Chip Resistor 1206 (3216 Metric) - Metal Element", Digikey Part Number=36-5108CT-ND, Manufacturer=Keystone, Mouser Part Number=534-5108, Operating Temperature Range=to, Power_W=500mW
TP1 TP10 TP13: library part CMP-0055138-2, "Test Point, Miniature, Black, TH", Color=Black, Manufacturer="Keystone Electronics", Supplier Part Number 1=36-5001-ND
TP2 TP3: library part CMP-0055137-2, "Test Point, Miniature, Red, TH", Color=Red, Manufacturer="Keystone Electronics", Supplier Part Number 1=36-5000-ND
TP5: library part CMP-0055139-2, "Test Point, Miniature, White, TH", Color=White, Manufacturer="Keystone Electronics", Supplier Part Number 1=36-5002-ND
TP7: library part CMP-0055141-2, "Test Point, Miniature, Yellow, TH", Color=Yellow, Manufacturer="Keystone Electronics", Supplier Part Number 1=36-5004-ND
TP14 TP15 TP16 TP17: library part CMP-0055113-1, "Terminal, Turret, TH, Double", Manufacturer=Keystone, Supplier Part Number 1=36-1502-2-ND
U1: library part CMP-0125639-1, Manufacturer="Texas Instruments", Operating Temperature Range=to, PartNumber=LMR604605SVBCRQ1
ZZ1: library part CMP-0003616-3
ZZ2: library part CMP-0077236-1
ZZ3: library part CMP-0077237-1
ZZ4: library part CMP-0077238-1

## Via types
v1: diameter 20, hole 8, Top Layer to Bottom Layer, tented both sides, 847 vias
v2: diameter 19.68, hole 7.87, Top Layer to Bottom Layer, tented both sides, 3 vias
v3: diameter 24, hole 8, Top Layer to Bottom Layer, tented both sides, 1 vias

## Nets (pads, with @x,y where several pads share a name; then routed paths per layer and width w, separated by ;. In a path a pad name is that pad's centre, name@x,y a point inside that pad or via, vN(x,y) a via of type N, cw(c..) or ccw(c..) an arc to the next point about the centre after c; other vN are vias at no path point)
BOOT: C1.1 U1.4 | length 32.4
  Top Layer w8: U1.4@1687.86,1829.66 C1.1@1718.83,1829.97 ; C1.1@1729.79,1829.66 C1.1@1730.78,1828.67
EN: R1.1 R4.2 TP3.1 U1.9 | length 911.4
  Top Layer w8: R1.1@1517.93,1786.29 1519.9,1786.29 1525.75,1792.13 1525.75,1796.79 1550.59,1821.63 1550.59,1825.05 1556.43,1830.89 R4.2@1558.4,1830.89 1574.14,1830.89 1575.38,1829.66 U1.9@1599.27,1829.66
  Top Layer w10: v1(1482.86,1784.7) 1483.65,1785.49 1517.14,1785.49 R1.1@1517.93,1786.29
  Signal Layer 2 w8: TP3.1@1105.16,2365 1106.16,2061 ; 1106.16,2060 v1(1482.86,1784.7)
FB: C7.2 R5.1 R9.2 U1.6 | length 128.1
  Top Layer w8: U1.6@1664.23,1867.06 1664.31,1867.13 1664.31,1885.49 R9.2@1684.31,1905.18 ; R9.2@1683.88,1904.98 R5.1@1765.46,1904.44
